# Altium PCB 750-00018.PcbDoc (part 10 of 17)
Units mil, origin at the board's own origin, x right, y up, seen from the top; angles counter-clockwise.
Board outline 7086.64 x 6299.21 mil, 8 copper layers (Top Layer, L2, L3, L4, L5, L6, L7, Bottom Layer), stack 60.6 mil thick; 1356 components, 1054 nets, 4851 pads, 4296 vias.
Unrouted connection lines stored in the file: 12.
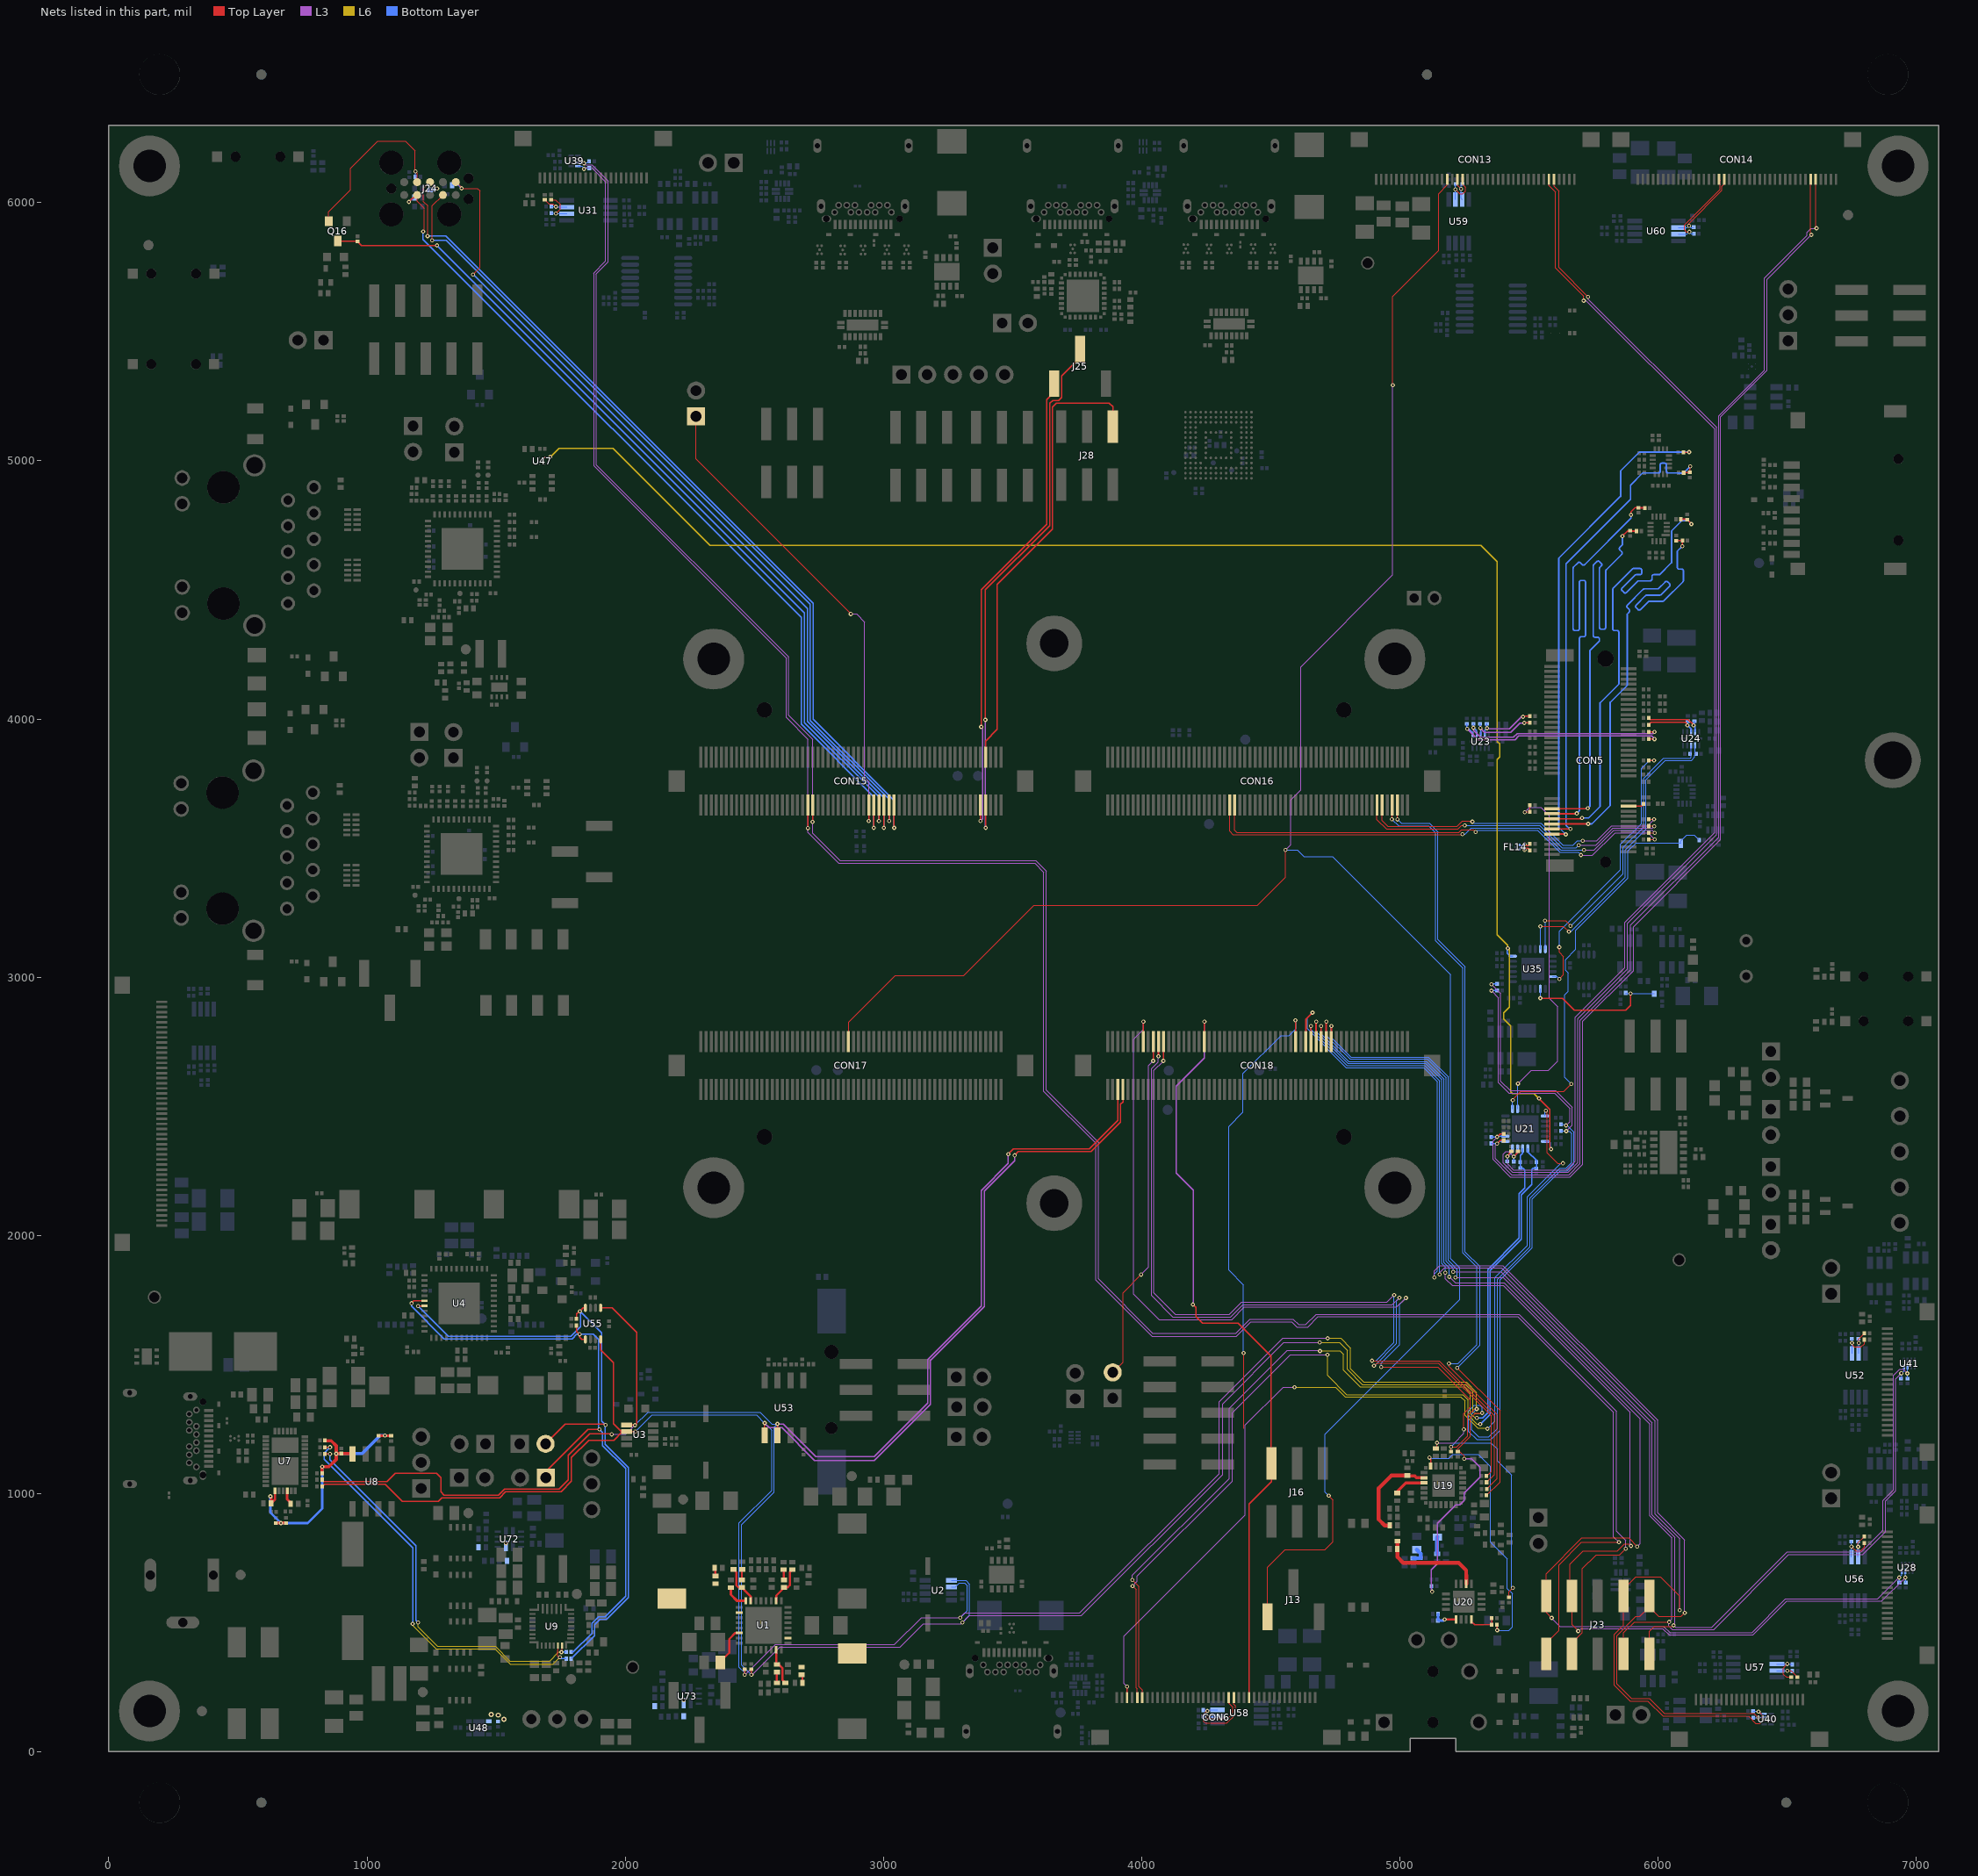
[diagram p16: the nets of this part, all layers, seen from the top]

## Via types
v1: diameter 16, hole 8, Top Layer to Bottom Layer, tented both sides, 3994 vias
v2: diameter 20, hole 10, Top Layer to Bottom Layer, tented both sides, 266 vias
v3: diameter 14, hole 7.87, Top Layer to Bottom Layer, tented both sides, 24 vias
v4: diameter 22, hole 12, Top Layer to Bottom Layer, tented both sides, 8 vias
v5: diameter 24, hole 12, Top Layer to Bottom Layer, tented both sides, 4 vias

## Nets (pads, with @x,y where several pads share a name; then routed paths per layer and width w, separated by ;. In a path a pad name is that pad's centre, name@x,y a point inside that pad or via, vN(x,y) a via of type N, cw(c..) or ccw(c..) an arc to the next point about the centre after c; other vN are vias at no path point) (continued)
"GPIO_C_5 / DSI_A_BL_EN / LVDS_A_BL_EN": CON6.27 CON18.82 J16.2 | length 3011.5
  Top Layer w5: v1(4198.33,1732.09) 4209.74,1720.68 4209.74,1685.04 4235.53,1659.26 4373.5,1659.26 4500.17,1532.59 4500.17,1118.66 J16.2@4501.95,1116.88 4501.95,1046.26 4415.76,960.06 CON6.27@4415.76,209.68
  Top Layer w6: CON18.82@4242.13,2750.44 v1@4242.13,2827.49
  L3 w5: v1(4198.33,1732.09) 4199.83,1733.59 4199.83,2175.39 4133.5,2241.71 4133.5,2577.65 4242.99,2687.14 v1(4242.99,2828.35)
"GPIO_C_6 / CAM_A_PWR": CON15.44 J23.1 R376.1 U39.4 | length 9216.5
  Top Layer w4: J23.1@5566.32,379.41 5566.32,421.21 5615.41,470.3 5615.41,723.87 5702.44,810.9 5847.78,810.9 v1(5848.36,811.47)
  Top Layer w5: CON15.44@2706.7,3666.88 2706.7,3577.98 v1(2707.58,3577.1)
  L3 w4: v1(1840,6130.2) 1845.27,6135.47 1869.47,6135.47 1924.42,6080.52 1924.42,5773.79 1877.84,5727.22 1877.84,4981.61 2623.28,4236.17 2623.28,4006.11 2707.58,3921.81 v1(2707.58,3577.1) 2707.58,3560.75 2826.66,3441.66 3585.75,3441.66 3620.92,3406.49 3620.92,2558.11 3822.26,2356.78 3822.26,1827.27 4039.82,1609.7 4366.02,1609.7 4421.93,1665.61 4580.38,1665.61 4600.61,1645.38 4643.06,1645.38 4683.35,1685.66 5456.19,1685.66 5827.71,1314.14 5827.71,832.12 v1(5848.36,811.47)
  Bottom Layer w4: U39.4@1816.76,6141.1 1831.06,6141.1 1840,6132.15 v1(1840,6130.2) 1843.92,6134.12 1860.57,6134.12 R376.1@1860.82,6133.87
"GPIO_C_7 / CAM_A_RST#": CON15.46 J23.3 R375.1 U39.3 | length 9149.4
  Top Layer w4: J23.3@5666.32,379.41 5666.32,420.46 5706.92,461.06 5706.92,709.15 5760.02,762.24 5851.24,762.24 v1(5874.7,785.7)
  Top Layer w5: v1(2725.36,3601.78) 2726.38,3602.8 CON15.46@2726.38,3666.88
  L3 w4: v1(1839.84,6152.52) 1845.9,6146.47 1871.08,6146.47 1933.34,6084.22 1933.34,5770.1 1886.76,5723.52 1886.76,4985.3 2632.2,4239.87 2632.2,4013.77 2725.36,3920.61 v1(2725.36,3601.78) 2725.36,3556.82 2830.81,3451.37 3590.29,3451.37 3631.29,3410.37 3631.29,2562.4 3832.62,2361.07 3832.62,1831.56 4042.72,1621.46 4364.67,1621.46 4419.08,1675.87 4586.65,1675.87 4608.24,1654.28 4635.43,1654.28 4675.46,1694.3 5462.2,1694.3 5838.11,1318.4 5838.11,854.32 5874.7,817.73 v1(5874.7,785.7)
  Bottom Layer w4: U39.3@1816.76,6154.88 1840.41,6154.88 v1@1840.41,6153.09 ; v1(1839.84,6152.52) v1@1840.41,6153.09 ; R375.1@1860.53,6159.56 1855.62,6154.65 1841.97,6154.65 v1@1840.41,6153.09
"GPIO_D_0 / CAM_B_PWR": CON18.32 J23.7 R390.1 U41.4 | length 5193.3
  Top Layer w4: J23.7@5866.32,379.41 5866.32,461.03 5908.15,502.86 v1(6042.9,502.86)
  Top Layer w6: CON18.32@4734.25,2750.44 v1@4734.25,2810.35
  L3 w4: v1(5214.71,1836.45) 5400.4,1836.45 5968.36,1268.48 5968.36,914.4 6053.57,829.19 6053.57,513.53 v1(6042.9,502.86) 6041.21,501.17 6041.21,486.9 6053.99,474.12 6215.71,474.12 6505.14,763.55 6792.34,763.55 6881.28,852.49 6881.28,971.54 6920.84,1011.1 6920.84,1444.95 v1(6941.53,1465.64)
  Bottom Layer w4: v1(4734.44,2810.54) 4734.44,2765.89 4809.53,2690.8 5110.02,2690.8 5187.68,2613.14 5187.68,1902.75 5222.33,1868.1 5222.33,1844.07 v1(5214.71,1836.45) ; R390.1@6940.39,1445.39 6941.53,1446.53 v1(6941.53,1465.64) 6943.69,1465.64 6952.6,1474.55 U41.4@6952.6,1490.47
"GPIO_D_1 / CAM_B_RST#": CON18.34 J23.9 R389.1 U41.3 | length 5155.3
  Top Layer w4: J23.9@5966.32,379.41 5966.32,467.43 5984.3,485.4 6056.14,485.4 v1(6060.21,489.46)
  Top Layer w6: CON18.34@4714.57,2750.44 v1@4714.57,2827.49
  L3 w4: v1(5206.68,1858.48) 5392.37,1858.48 5976.87,1273.98 5976.87,917.93 6064.32,830.47 6064.32,493.58 v1(6060.21,489.46) 6067.53,482.14 6208.53,482.14 6500.69,774.3 6787.89,774.3 6870.53,856.94 6870.53,974.01 6911.06,1014.54 6911.06,1457.52 6935.51,1481.97 6948.57,1481.97 6965.13,1465.4 v1(6965.13,1465.23)
  Bottom Layer w4: v1(4715.43,2828.35) 4715.43,2773.46 4806.18,2682.71 5106.67,2682.71 5179.6,2609.79 5179.6,1898.92 5206.68,1871.83 v1(5206.68,1858.48) ; R389.1@6965.54,1445.25 6965.13,1445.65 v1(6965.13,1465.23) 6966.38,1466.48 U41.3@6966.38,1490.47
"GPIO_D_2 / CAM_C_PWR": CON18.36 J23.2 R372.1 U28.4 | length 4991.3
  Top Layer w4: v1(5587.76,518.34) 5566.32,539.77 J23.2@5566.32,603.82 5566.32,689.88 5704.4,827.96 5886.37,827.96 5919.04,795.29 v1(5919.04,794.42)
  Top Layer w6: CON18.36@4694.88,2750.44 v1@4694.88,2810.35
  L3 w4: v1(5191.37,1839.43) 5214.35,1816.46 5403.16,1816.46 5930.69,1288.93 5930.69,806.07 v1(5919.04,794.42) ; v1(5587.76,518.34) 5619.98,486.12 6020.51,486.12 6045.62,461 6363.33,461 6494.11,591.79 6850.02,591.79 v1(6933.2,674.97)
  Bottom Layer w4: v1(4695.07,2810.54) 4695.07,2781.11 4802.45,2673.72 5102.95,2673.72 5170.61,2606.07 5170.61,1894.67 5191.37,1873.91 v1(5191.37,1839.43) ; R372.1@6934.29,655.18 6933.2,656.27 v1(6933.2,674.97) 6944.03,685.79 U28.4@6944.03,699.7
"GPIO_D_3 / CAM_C_RST#": CON18.38 J23.4 R371.1 U28.3 | length 4868.3
  Top Layer w4: v1(5690.38,467.57) 5666.32,491.63 J23.4@5666.32,603.82 5658.16,611.98 5658.16,725.87 5709.53,777.24 5841.97,777.24 5869.58,804.84 5887.01,804.84 v1(5894.59,797.26)
  Top Layer w6: CON18.38@4675.2,2750.44 v1@4675.2,2827.49
  L3 w4: v1(5176.06,1855.68) 5176.06,1832.36 5202.66,1805.76 5400.95,1805.76 5891.77,1314.95 5891.77,800.09 v1(5894.59,797.26) ; v1(5690.38,467.57) 5700.29,477.48 6016.93,477.48 6042.04,452.37 6366.9,452.37 6497.69,583.15 6865.93,583.15 v1(6957.55,674.77)
  Bottom Layer w4: v1(4676.06,2828.35) 4676.06,2788.77 4799.13,2665.7 5099.63,2665.7 5162.59,2602.74 5162.59,1890.81 5176.06,1877.33 v1(5176.06,1855.68) ; U28.3@6957.81,699.7 6957.81,675.03 v1(6957.55,674.77) 6959.63,672.69 R371.1@6959.63,655.18
"GPIO_D_4 / CAM_D_PWR": CON18.40 J23.8 R388.1 U40.4 | length 4706.2
  Top Layer w4: v1(6083.84,548.55) 6083.84,602.03 6008.83,677.04 5914.21,677.04 5866.32,629.15 J23.8@5866.32,603.82 5866.32,491.02 5830.57,455.27 5830.57,258.18 5891.97,196.78 5959.51,196.78 6018.39,137.9 6350.45,137.9 6377.99,110.37 6394.32,110.37 6403.97,120.02 6403.97,141.72 6390.55,155.14 v1(6388.84,155.14)
  Top Layer w6: CON18.40@4655.51,2750.44 v1@4655.51,2810.35
  L3 w4: v1(5154.03,1848.77) 5154.03,1855.74 5172.66,1874.37 5394.24,1874.37 5987.98,1280.63 5987.98,920.49 6083.84,824.63 v1(6083.84,548.55)
  Bottom Layer w4: v1(4655.7,2810.54) 4655.7,2797.03 4795.58,2657.14 5096.08,2657.14 5154.03,2599.2 v1(5154.03,1848.77) ; R388.1@6367.62,156.78 6387.19,156.78 v1(6388.84,155.14) 6396.73,147.25 U40.4@6410.66,147.25
"GPIO_D_5 / CAM_D_RST#": CON18.42 J23.10 R387.1 U40.3 | length 4731.7
  Top Layer w4: v1(6102.93,538.07) 6088.43,523.57 6002.5,523.57 5966.32,559.74 J23.10@5966.32,603.82 5966.32,560.37 5929.63,523.68 5913.86,523.68 5840.28,450.1 5840.28,262.96 5896.39,206.85 5966.23,206.85 6023.62,149.46 6370.92,149.46 v1(6388.01,132.37)
  Top Layer w6: CON18.42@4635.83,2750.44 4635.83,2837.04 v1(4661.33,2862.55)
  L3 w4: v1(5133.42,1837.07) 5133.42,1861.78 5154.44,1882.79 5399.28,1882.79 5998.47,1283.6 5998.47,924.83 6102.93,820.37 v1(6102.93,538.07)
  Bottom Layer w4: v1(4661.33,2862.55) 4641.35,2842.56 4641.35,2799.99 4792.25,2649.09 5092.75,2649.09 5145.97,2595.86 5145.97,1862.73 5133.42,1850.18 v1(5133.42,1837.07) ; R387.1@6367.8,131.26 6386.9,131.26 v1(6388.01,132.37) 6389.12,133.47 U40.3@6410.66,133.47
GPIO_D_6: CON15.113 J28.6 | length 1786
  Top Layer w5: CON15.113@3395.67,3851.92 3395.67,3914.9 3440.35,3959.57 3440.35,4520.83 3654.82,4735.31 3654.82,5208.47 3669.95,5223.6 3873.3,5223.6 3888.03,5208.87 J28.6@3888.03,5132.38
"GPIO_D_7 / SPI_C_CS1#": CON18.46 SB1.2 | length 1814.1
  Top Layer w4: v1(4394.43,1544.31) 4394.8,1543.94 4394.8,1252.38
  Top Layer w6: v1(4595,2832.55) 4596.46,2831.09 CON18.46@4596.46,2750.44
  Bottom Layer w4: v1(4394.43,1544.31) 4394.43,1807.47 4336.89,1865.01 4336.89,2421.82 4392.36,2477.29 4392.36,2627.49 4539.18,2774.32 4570.87,2774.32 4597.18,2800.63 4597.18,2830.37 v1(4595,2832.55)
HP_JD: R201.1 U19.12 | length 1039
  Top Layer w5: v1(5115.07,1139.27) 5119.48,1134.86 U19.12@5119.48,1106.54 ; R201.1@5375.56,492.02 5376.99,490.6 v1(5376.99,470.79)
  Bottom Layer w4: v1(5115.07,1139.27) 5118.54,1135.8 5188.57,1135.8 5204.01,1151.24 5303.63,1151.24 5350.45,1104.42 5350.45,812.1 5415.75,746.81 5415.75,632.18 5435.44,612.48 5435.44,483.25 5422.98,470.79 v1(5376.99,470.79)
HP_MICL1-: C212.1 U19.15 | length 123.7
  Top Layer w12: C212.1@4990.14,1002.22 4990.14,1008.5 5023.23,1041.58 U19.15@5093.89,1041.58
HPL: C202.2 FB5.1 R187.1 | length 65.7
  Bottom Layer w15: FB5.1@5144.76,766.45 5143.98,767.23 R187.1@5143.98,797.72 5143.98,830.76 C202.2@5144.76,831.54
HPR: C203.2 FB6.1 R191.2 | length 68.3
  Bottom Layer w15: FB6.1@5051.89,749.67 5079.87,749.67 R191.2@5081.16,750.96 5081.16,767.01 C203.2@5065.31,782.86
I2C_A_SCL: CON18.115 R17.1 R55.2 R190.1 R192.1 R302.1 R329.1 U2.5 U3.5 U53.6 U55.5 | length 13471.4
  Top Layer w4: v1(5248.47,1134.73) 5248.47,1146.01 5232.4,1162.08 R190.1@5224,1162.08 5224,1172.23 5273.41,1221.64 5273.41,1293.16 5292.6,1312.35 v1(5318.83,1312.35)
  Top Layer w5: R55.2@826.11,1053.79 832.76,1047.14 1077.32,1047.14 1108.54,1078.36 1269.94,1078.36 1286.03,1062.27 1286.03,1007.14 1298.84,994.32 1509.45,994.32 1532.37,1017.24 1742.98,1017.24 1778.7,1052.95 1778.7,1148.02 1861.84,1231.17 1945.1,1231.17 v1(1946.94,1229.33) ; U55.5@1904.57,1719.36 1948.59,1719.36 2044.02,1623.93 2044.02,1270.91 2038.85,1265.74 U3.5@2005.39,1265.74 ; R17.1@2488.19,319.89 2488.19,298.95 v1(2488.58,298.56) ; v1(2589.11,1269.85) 2589.85,1269.1 U53.6@2589.85,1225.9 ; v1(3483.35,2314.83) 3503.1,2334.59 3797.35,2334.59 3907.48,2444.72 CON18.115@3907.48,2565.4
  L3 w4: v1(1946.94,1229.33) 2002.44,1229.33 v1(2037.97,1264.86) ; v1(2488.58,298.56) 2491.12,298.56 2598.09,405.54 3063.65,405.54 3154.42,496.31 3300.85,496.31 v1(3305.5,500.95) 3332.57,528.02 3766.81,528.02 4313.06,1074.27 4313.06,1346.82 4550.98,1584.75 v1(4689.97,1584.75) ; v1(5353.98,2947.81) 5381.4,2920.39 5381.4,2592.24 5422.58,2551.06 5598.81,2551.06 5657.93,2491.94 5657.93,2440.42 v1(5643.4,2425.89)
  L3 w5: v1(2589.11,1269.85) 2612.13,1269.85 2738.2,1143.78 2964,1143.78 3171.24,1351.02 3171.24,1518.95 3378.88,1726.59 3378.88,2173.61 3483.35,2278.08 v1(3483.35,2314.83) ; v1(5125.07,620.18) 5122.03,623.22 5122.03,705.14 5144.76,727.86 5144.76,884.6 5216.26,956.1 5231.17,956.1 5248.08,973.01 5248.08,1002.63 5309.26,1063.8 5309.26,1103.14 5277.67,1134.73 v1(5248.47,1134.73)
  L6 w4: v1(4689.97,1584.75) 4766.15,1584.75 4796.07,1554.83 4796.07,1481.29 4854.53,1422.83 5254.07,1422.83 5282.65,1394.25 5282.65,1317.18 5290.66,1309.18 5315.65,1309.18 v1(5318.83,1312.35)
  Bottom Layer w4: v1(2037.97,1264.86) 2088.82,1315.71 2521.83,1315.71 2567.7,1269.85 v1(2589.11,1269.85) 2577.19,1257.93 2577.19,1006.18 2451.42,880.4 2451.42,335.72 v1(2488.58,298.56) ; U2.5@3263.47,663.75 3318.77,663.75 3333.19,649.34 3333.19,528.64 v1(3305.5,500.95) ; v1(5318.83,1312.35) 5318.83,1333.75 5310.01,1342.57 5288.1,1342.57 5266.19,1320.66 5266.19,1240.95 5297.99,1209.14 5352.22,1209.14 5389,1245.92 5389,1829 5512.71,1952.72 5512.71,2141.39 5621.8,2250.48 5647.58,2250.48 5674.26,2277.16 5674.26,2399.03 5643.3,2429.99 R302.1@5623.53,2429.99
  Bottom Layer w5: R192.1@5122.6,641.5 5122.6,622.66 v1(5125.07,620.18) ; v1@5354.77,2948.6 R329.1@5376.29,2948.6
I2C_A_SCL_3V3: J37.2 R280.2 R436.1 U4.43 U55.8 | length 2633.3
  Top Layer w5: v1(1197.45,1726.46) 1198.03,1727.04 U4.43@1222.82,1727.04 ; J37.2@1691.42,1192.67 1766.96,1268.2 1920.47,1268.2 v1(1923.18,1265.49) ; R436.1@1812.27,1676.84 1812.27,1695.02 1823.64,1706.39 v1(1824.31,1706.39) 1824.31,1707.06 1836.61,1719.36 U55.8@1845.52,1719.36
  Bottom Layer w5: v1(1197.45,1726.46) 1197.89,1726.02 1314.63,1609.28 1789.13,1609.28 1826.78,1646.92 v1@1826.78,1703.92 ; R280.2@1790.69,360.59 1791.15,360.59 1880.92,450.36 1880.92,492.81 1901.05,512.94 1926.72,512.94 2011.96,598.18 2011.96,1101.04 1922.39,1190.61 1922.39,1264.7 v1(1923.18,1265.49) 1907.53,1281.14 1907.53,1623.17 v1@1826.78,1703.92 ; v1(1824.31,1706.39) v1@1826.78,1703.92
I2C_A_SDA: CON18.113 R16.1 R56.2 R189.1 R194.1 R209.1 R328.1 U2.6 U3.6 U53.5 U55.4 | length 13267.2
  Top Layer w4: R189.1@5198.09,1162.38 5198.09,1180.27 v1(5197.75,1180.61) 5220.12,1180.61 5263.05,1223.55 5263.05,1302.62 5287.99,1327.56 v1(5297.26,1327.56) ; R194.1@5422.49,598.18 5422.49,619.85 v1(5437.17,634.53)
  Top Layer w5: R56.2@826.11,1027.67 835.3,1036.87 1070.16,1036.87 1136.8,970.22 1275.09,970.22 1288.92,984.05 1513.2,984.05 1536.48,1007.33 1751.12,1007.33 1790.94,1047.15 1790.94,1138.99 1858.63,1206.68 1955.57,1206.68 1989.05,1240.15 1985.06,1240.15 1953.68,1271.53 1953.68,1507.86 1904.57,1556.96 U55.4@1904.57,1597.31 ; U3.6@2005.39,1240.15 2038.51,1240.15 v1(2038.65,1240.01) ; R16.1@2462.44,320.07 2462.44,298.5 v1(2462.51,298.43) ; v1(2539.67,1273.24) 2539.85,1273.05 U53.5@2539.85,1225.9 ; v1(3507.75,2309.95) 3522.12,2324.32 3804.28,2324.32 3918.21,2438.25 3918.21,2508.66 3927.17,2517.62 CON18.113@3927.17,2565.4
  L3 w4: v1(2462.51,298.43) 2464.99,298.43 2581.54,414.98 3042.76,414.98 3147.45,519.66 v1(3297.18,519.66) 3314.69,537.17 3759.69,537.17 4300.24,1077.72 4300.24,1355.52 4546.17,1601.45 v1(4720.42,1601.45) ; v1(5354.14,2972.85) 5390.36,2936.63 5390.36,2596.94 5426.87,2560.43 5603.1,2560.43 5667.11,2496.42 5667.11,2426.63 v1(5644.02,2403.53)
  L3 w5: v1(2539.67,1273.24) 2558.3,1254.61 2606.75,1254.61 2732.76,1128.6 2963.48,1128.6 3181.07,1346.19 3181.07,1515.28 3391.16,1725.36 3391.16,2171.81 3507.75,2288.41 v1(3507.75,2309.95)
  L6 w4: v1(4720.42,1601.45) 4771.03,1601.45 4808.81,1563.67 4808.81,1482.99 4860.21,1431.6 5257.9,1431.6 5297.26,1392.24 v1(5297.26,1327.56)
  Bottom Layer w4: v1(2038.65,1240.01) 2103.34,1304.71 2508.2,1304.71 v1(2539.67,1273.24) 2567.6,1245.31 2567.6,1012.45 2441.28,886.14 2441.28,327.97 2462.51,306.75 v1(2462.51,298.43) ; U2.6@3263.47,638.16 3277.86,638.16 3293.18,653.49 3313.61,653.49 3323.84,643.26 3323.84,546.32 v1(3297.18,519.66) ; v1(5197.75,1180.61) 5213.84,1196.7 5352.75,1196.7 5377.53,1171.92 5377.53,1126.6 5433.08,1071.05 5433.08,638.63 v1(5437.17,634.53) ; v1(5297.26,1327.56) 5277.99,1308.29 5277.99,1246.42 5305.48,1218.93 5344.84,1218.93 5378.01,1252.1 5378.01,1830.75 5503.65,1956.39 5503.65,2144.44 5619.75,2260.54 5643.81,2260.54 5665.72,2282.45 5665.72,2394.37 5656.56,2403.53 v1(5644.02,2403.53) 5643,2404.55 R209.1@5623.53,2404.55
  Bottom Layer w5: v1@5354.92,2973.64 R328.1@5376.29,2973.64
I2C_A_SDA_3V3: J42.1 R278.2 R435.1 U4.42 U55.1 | length 2594.5
  Top Layer w5: v1(1171.82,1737.08) 1181.47,1746.73 U4.42@1222.82,1746.73 ; J42.1@1692.8,1061.54 1692.8,1086.23 1855.28,1248.72 v1(1900.08,1248.72) ; R435.1@1812.27,1650.9 1812.27,1628.11 v1(1823.41,1616.97) 1823.41,1605.72 1831.82,1597.31 U55.1@1845.52,1597.31
  Bottom Layer w5: v1(1171.82,1737.08) 1171.82,1725.63 1298.83,1598.63 1793.79,1598.63 1812.14,1616.97 v1(1823.41,1616.97) 1876.36,1616.97 1896.93,1596.4 1896.93,1251.86 v1(1900.08,1248.72) 1911.97,1236.82 1911.97,1186.05 2001.36,1096.65 2001.36,602.57 1922.33,523.54 1896.66,523.54 1870.32,497.2 1870.32,458.67 1798.54,386.89 R278.2@1790.78,386.89
I2C_B_MCU_SCL: CON15.112 J25.1 | length 1918.4
  Top Layer w5: v1@3375.99,3604.75 CON15.112@3375.99,3666.88 ; v1(3378.34,3969.56) 3378.34,4499.97 3632.68,4754.32 3632.68,5236.59 3660.62,5264.52 J25.1@3660.62,5338.03
  L3 w5: v1(3375.89,3604.65) 3384.33,3613.09 3384.33,3963.56 v1(3378.34,3969.56)
I2C_B_MCU_SDA: CON15.114 J25.2 | length 2149.6
  Top Layer w5: v1(3394.75,3996.64) 3394.75,4500.57 3643.87,4749.69 3643.87,5222.67 3655.25,5234.05 3678.04,5234.05 3689.91,5245.92 3689.91,5329.08 3761.23,5400.39 J25.2@3761.23,5432.54 ; v1(3395.58,3578.53) 3395.67,3578.62 CON15.114@3395.67,3666.88 ; J25.2@3760.56,5432.54 J25.2@3760.56,5471.94
  L3 w5: v1(3394.75,3996.64) 3394.75,3584.95 3391.96,3582.15 v1(3395.58,3578.53)
I2C_C_SCL: CON6.23 R492.2 U58.2 | length 232.9
  Top Layer w4: v1(4254.45,134.72) 4254.45,130.78 4256.58,128.65 4333.13,128.65 4353,148.53 4353,172.17 4337.02,188.16 CON6.23@4337.02,209.68
  Bottom Layer w4: R492.2@4242.18,135.83 4243.25,136.9 4252.27,136.9 v1(4254.45,134.72) 4256.62,136.9 U58.2@4293.42,136.9
I2C_C_SDA: CON6.24 R491.2 U58.3 | length 311.5
  Top Layer w4: v1(4254.09,158.01) 4251.61,158.01 4239.65,146.05 4239.65,117.8 4246.77,110.68 4330.02,110.68 4362.73,143.39 4362.73,178.33 4356.7,184.36 CON6.24@4356.7,209.68
  Bottom Layer w4: R491.2@4242.18,161.22 4243.46,162.5 4249.6,162.5 v1(4254.09,158.01) 4258.58,162.5 U58.3@4293.42,162.5
I2C_CAM_A_SCL: R367.1 R453.2 U31.2 | length 145.5
  Top Layer w4: R367.1@1712.84,6011.06 1730.03,6011.06 1748.21,5992.88 1748.21,5974.4 v1(1731.81,5958)
  Bottom Layer w4: R453.2@1713.15,5958.85 1730.96,5958.85 v1(1731.81,5958) 1732.31,5957.5 1772.87,5957.5 U31.2@1773.32,5957.05
I2C_CAM_A_SDA: R368.1 R452.2 U31.3 | length 115
  Top Layer w4: R368.1@1688.35,6010.86 1703.67,5995.55 1719.88,5995.55 v1(1731.55,5983.88)
  Bottom Layer w4: R452.2@1713.36,5984.34 1731.09,5984.34 v1(1731.55,5983.88) 1732.78,5982.65 U31.3@1773.32,5982.65
I2C_CAM_B_SCL: R379.1 R455.2 U52.2 | length 134.5
  Top Layer w4: v1(6750.93,1583.05) 6750.93,1576.08 6758.95,1568.06 6786.55,1568.06 6799,1580.51 R379.1@6799,1596
  Bottom Layer w4: R455.2@6750.15,1597.79 6751.09,1596.85 U52.2@6751.09,1542.72
I2C_CAM_B_SDA: R380.1 R454.2 U52.3 | length 102.1
  Top Layer w4: v1(6776.84,1583.05) 6776.84,1598.59 R380.1@6798.83,1620.58
  Bottom Layer w4: R454.2@6775.81,1597.79 6776.69,1596.91 U52.3@6776.69,1542.72
I2C_CAM_C_SCL: R369.1 R457.2 U56.2 | length 140.5
  Top Layer w4: v1(6748.89,794.67) 6766.54,777.02 6783.41,777.02 6798.54,792.15 R369.1@6798.54,808.66
  Bottom Layer w4: R457.2@6748.76,814.83 6748.76,794.8 v1(6748.89,794.67) 6749.06,794.5 U56.2@6749.06,754.21
I2C_CAM_C_SDA: R370.1 R456.2 U56.3 | length 110.1
  Top Layer w4: v1(6774.63,794.03) 6774.63,809.69 R370.1@6798.54,833.59
  Bottom Layer w4: R456.2@6774.29,814.66 6774.29,794.37 v1(6774.63,794.03) U56.3@6774.66,754.21
I2C_CAM_D_SCL: R381.1 R459.2 U57.2 | length 142.7
  Top Layer w4: v1(6500.49,340.24) 6484.55,324.3 6484.55,300.81 6496.3,289.06 R381.1@6515.2,289.06
  Bottom Layer w4: U57.2@6459.98,339.78 6500.03,339.78 v1(6500.49,340.24) 6502.44,338.28 R459.2@6520.18,338.28
I2C_CAM_D_SDA: R382.1 R458.2 U57.3 | length 109.3
  Top Layer w4: v1(6500.33,313.42) 6514.69,313.42 R382.1@6539.01,289.09
  Bottom Layer w4: U57.3@6459.98,314.18 6499.57,314.18 v1(6500.33,313.42) R458.2@6520.17,313.42
I2C_charger_SCL: R210.2 R280.1 U9.14 | length 1587.4
  Top Layer w4: U9.14@1739.2,411.75 1739.2,395.9 1737.6,394.3 1737.6,368.93 1740.68,365.84 v1(1746.36,365.84)
  Top Layer w5: R210.2@837.1,1179.45 v1(856.52,1179.45)
  L6 w4: v1(1176.44,495.35) 1176.44,490.99 1268.13,399.3 1494.41,399.3 1554.62,339.09 1719.61,339.09 v1(1746.36,365.84)
  Bottom Layer w5: v1(856.52,1179.45) 834.28,1157.21 834.28,1133.58 1177.92,789.94 1177.92,496.82 v1(1176.44,495.35) ; v1@1745.93,365.41 1745.93,360.59 R280.1@1771.01,360.59
I2C_charger_SDA: R273.2 R278.1 U9.15 | length 1501.2
  Top Layer w4: v1(1752.61,386.06) 1754.05,386.06 1754.94,386.96 U9.15@1754.94,411.75
  Top Layer w5: R273.2@837.1,1153.58 v1(856.52,1153.58)
  L6 w4: v1(1197.7,500.55) 1197.7,482.96 1272.55,408.12 1496.99,408.12 1553.35,351.75 1708.2,351.75 1742.51,386.06 v1(1752.61,386.06)
  Bottom Layer w5: v1(856.52,1153.58) 856.52,1131.27 1188.89,798.9 1188.89,509.36 v1(1197.7,500.55) ; v1(1752.61,386.06) 1753.43,386.89 R278.1@1771.1,386.89
I2C_D_SCL: CON13.23 R496.2 U59.2 | length 199.4
  Top Layer w4: v1(5215.17,6051.17) 5232.69,6033.64 5243.52,6033.64 5254.35,6044.47 5254.35,6059.43 5242.4,6071.38 CON13.23@5242.4,6089.26
  Bottom Layer w4: v1(5215.17,6051.17) 5215.31,6051.03 U59.2@5215.31,6012.35 5215.31,6070.7 R496.2@5216.35,6071.75
I2C_D_SDA: CON13.24 R495.2 U59.3 | length 105.7
  Top Layer w4: CON13.24@5222.72,6089.26 5222.72,6066.69 v1(5236.51,6052.89)
  Bottom Layer w4: U59.3@5240.91,6012.35 5236.51,6016.74 v1(5236.51,6052.89) 5236.51,6065.93 R495.2@5242.33,6071.75
I2C_E_SCL: CON14.23 R501.2 U60.2 | length 305
  Top Layer w4: v1(6119.24,5910.03) 6117.8,5911.48 6117.8,5917.56 6247.63,6047.39 6247.63,6063.76 6255.81,6071.95 CON14.23@6255.81,6090.59
  Bottom Layer w4: U60.2@6078.35,5902.95 6112.15,5902.95 v1(6119.24,5910.03) 6126.65,5902.63 6135.62,5902.63 R501.2@6137.99,5905
I2C_E_SDA: CON14.24 R500.2 U60.3 | length 343.3
  Top Layer w4: v1(6120.68,5886.85) 6109.1,5886.85 6101.88,5894.07 6101.88,5914.24 6239.17,6051.53 6239.17,6087.55 CON14.24@6236.13,6090.59
  Bottom Layer w4: U60.3@6078.35,5877.35 6111.18,5877.35 v1(6120.68,5886.85) 6128.22,5879.31 R500.2@6138.14,5879.31
I2S_A_BITCLK: CON16.116 R184.1 | length 2996.3
  Top Layer w4: CON16.116@4990.16,3666.88 4990.16,3611.6 v1(4990.63,3611.13) ; v1(5221.44,1486.98) 5387.46,1320.95 5387.46,1045.08 R184.1@5335.45,993.06
  Bottom Layer w4: v1(4990.63,3611.13) 5005.74,3596.01 5114.27,3596.01 5147.58,3562.7 5147.58,3145.01 5252.51,3040.08 5252.51,1935.67 5309.27,1878.92 5309.27,1574.81 v1(5221.44,1486.98)
I2S_A_DATA_IN: CON18.98 R186.1 | length 3118.1
  Top Layer w4: v1(4891.59,1514.64) 5152.32,1514.64 5366.35,1300.62 5366.35,1074.21 R186.1@5335.97,1043.83
  Top Layer w6: v1@4084.65,2676.53 CON18.98@4084.65,2750.44 CON18.98@4084.65,2753.58
  L3 w4: v1(4083.78,2675.67) 4047.51,2639.4 4047.51,1776.57 4130.39,1693.69 4339.87,1693.69 4387.15,1740.97 4949.68,1740.97 v1(4977.58,1768.87)
  Bottom Layer w4: v1(4891.59,1514.64) 4906.5,1514.64 4977.58,1585.72 v1(4977.58,1768.87)
I2S_A_DATA_OUT: CON18.100 R185.1 | length 3116.5
  Top Layer w4: v1(4899.63,1495.21) 4910.58,1506.16 5148.93,1506.16 5354.58,1300.51 5354.58,1085.1 5337.99,1068.5 R185.1@5335.04,1068.5
  Top Layer w6: v1@4064.96,2693.67 CON18.100@4064.96,2753.58
  L3 w4: v1(4064.77,2693.48) 4064.77,2672.37 4037.64,2645.24 4037.64,1766.35 4120.42,1683.56 4344.03,1683.56 4391.86,1731.39 4970.5,1731.39 v1(4998.15,1759.03)
  Bottom Layer w4: v1(4899.63,1495.21) 4901.42,1495.21 4987.53,1581.32 4987.53,1748.41 v1(4998.15,1759.03)
I2S_A_LRCLK: CON16.114 R183.1 | length 3013.3
  Top Layer w4: v1(4968.96,3611.81) 4969.81,3612.66 4969.81,3666.22 CON16.114@4970.47,3666.88 ; v1(5189.97,1503.82) 5189.97,1493.44 5376.68,1306.73 5376.68,1058.77 R183.1@5335.86,1017.94
  Bottom Layer w4: v1(4968.96,3611.81) 4995.42,3585.35 5111.33,3585.35 5137.96,3558.71 5137.96,3141.03 5243.67,3035.32 5243.67,1932.05 5298.16,1877.55 5298.16,1577.18 5224.81,1503.82 v1(5189.97,1503.82)
I2S_AB_MCLK: CON18.106 R419.2 | length 3268.1
  Top Layer w4: v1(4927.33,1489.63) 5147.13,1489.63 5273.52,1363.24 5273.52,1335.76 5247.78,1310.03 v1(5247.78,1248.39) ; R419.2@5139.83,1174.31 5143.2,1177.68 v1(5143.2,1196.53)
  Top Layer w6: CON18.106@4005.91,2750.44 v1@4005.91,2827.49
  L3 w4: v1(4006.77,2828.35) 4006.77,2798.03 3968.96,2760.22 3968.96,1772.93 4067.53,1674.35 4349.11,1674.35 4396.87,1722.11 4987.84,1722.11 v1(5023.35,1757.62) ; v1(5143.2,1196.53) 5210.93,1196.53 5247.78,1233.37 v1(5247.78,1248.39)
  Bottom Layer w4: v1(4927.33,1489.63) 4927.33,1505.8 4998.66,1577.13 4998.66,1732.93 v1(5023.35,1757.62)
"I2S_AB_RST / GPIO_A_5": CON18.102 J39.2 | length 1348.2
  Top Layer w4: J39.2@3887.85,1469.4 3927.17,1508.71 3927.17,1777.58 v1(3997.76,1848.17)
  Top Layer w6: v1@4045.28,2676.53 CON18.102@4045.28,2750.44 CON18.102@4045.28,2753.58
  L3 w4: v1(3997.76,1848.17) 4027.38,1877.79 4027.38,2658.64 v1(4044.41,2675.67)
I2S_B_BITCLK: CON16.52 R268.1 | length 1848.6
  Top Layer w4: CON16.52@4360.24,3666.88 4360.24,3568.87 4368.19,3560.91 5228.11,3560.91 5237.87,3570.68 5284.98,3570.68 v1(5293.3,3562.36) ; R268.1@5963.24,3533.91 5986.31,3533.91 v1(5986.45,3533.77)
  L3 w4: v1(5700.98,3472.96) 5702.49,3471.45 5745.08,3471.45 5833.16,3559.53 5960.69,3559.53 v1(5986.45,3533.77)
  Bottom Layer w4: v1(5293.3,3562.36) 5299.89,3568.95 5533.57,3568.95 5619.16,3483.36 5690.59,3483.36 v1(5700.98,3472.96)
I2S_B_DATA_IN: CON16.108 R266.1 | length 1242.9
  Top Layer w4: CON16.108@4911.42,3666.88 4911.42,3610.31 4947.71,3574.02 5225.23,3574.02 5239.53,3588.32 v1(5251.13,3588.32) ; R266.1@5963.14,3585.33 5983.75,3585.33 v1(5984.62,3584.45)
  L3 w4: v1(5692.33,3511.34) 5758.86,3511.34 5824.76,3577.24 5977.4,3577.24 v1(5984.62,3584.45)
  Bottom Layer w4: v1(5251.13,3588.32) 5252.19,3587.26 5541.99,3587.26 5627.71,3501.54 5682.53,3501.54 v1(5692.33,3511.34)
I2S_B_DATA_OUT: CON16.110 R265.1 | length 1232.1
  Top Layer w4: CON16.110@4931.1,3666.88 4931.1,3606.29 4952.53,3584.87 5221.39,3584.87 5241.59,3605.07 5277.8,3605.07 v1(5280.66,3602.21) ; R265.1@5963.22,3611.33 5984.04,3611.33 v1(5984.19,3611.17)
  L3 w4: v1(5708.23,3528.69) 5763.07,3528.69 5820.38,3586 5959.02,3586 v1(5984.19,3611.17)
  Bottom Layer w4: v1(5280.66,3602.21) 5287.09,3595.78 5546.32,3595.78 5630.71,3511.39 5670.44,3511.39 5687.74,3528.69 v1(5708.23,3528.69)
I2S_B_LRCLK: CON16.50 R267.1 | length 1858.1
  Top Layer w4: CON16.50@4340.55,3666.88 4340.55,3565.07 4353.83,3551.79 5239.91,3551.79 v1(5241.62,3553.5) ; R267.1@5963.04,3559.47 v1@5985.85,3559.47
  L3 w4: v1(5713.3,3492.38) 5752.94,3492.38 5829.37,3568.81 5976.52,3568.81 v1(5986.3,3559.04)
  Bottom Layer w4: v1(5241.62,3553.5) 5252.19,3553.5 5276.92,3578.23 5537.42,3578.23 5623.26,3492.38 v1(5713.3,3492.38)
INT_B: R195.2 R198.2 U20.13 | length 97.4
  Top Layer w10: v1@5173.12,512.44 U20.13@5217.48,512.44
  Bottom Layer w10: R198.2@5147,533.59 R195.2@5147,508.39 5169.06,508.39 v1(5173.12,512.45)
IO_exp_reset: U21.12 U35.24 U47.4 | length 6417.5
  Top Layer w5: U47.4@1687.75,5014.54 1709.69,5014.54 v1(1709.9,5014.76) ; v1@5538.75,2530.19 5580.61,2488.32 5580.61,2339.45 v1(5585.89,2334.17)
  L6 w5: v1(1709.9,5014.76) 1743.63,5048.48 1952.38,5048.48 2328.45,4672.41 5313.63,4672.41 5376.97,4609.06 5376.97,3912.98 5386.67,3903.28 5386.67,3852.74 5376.97,3843.05 5376.97,3165.26 5417.82,3124.42 v1(5417.82,3111.97) 5423.69,3106.1 5423.69,2884.54 5401.87,2862.72 5401.87,2837.7 5429.38,2810.18 5429.38,2555.43 5435.67,2549.14 5519.97,2549.14 v1(5538.75,2530.36)
  Bottom Layer w5: v1(5417.82,3111.97) 5415.98,3110.14 5415.98,3092.84 5427.75,3081.08 U35.24@5437.38,3081.08 ; U21.12@5562.04,2363.96 5578.37,2363.96 5582.93,2359.4 5582.93,2337.13 v1(5585.89,2334.17)
JTAG_nTRST: CON15.72 Q16.3 R366.2 | length 3390.1
  Top Layer w5: Q16.3@886.36,5851.03 R366.2@961.19,5851.03 ; R366.2@962.64,5849.58 977.95,5834.27 v1(1271.02,5834.27) ; v1@2982.29,3604.75 CON15.72@2982.29,3666.88
  Bottom Layer w5: v1(1271.02,5834.27) 2694.23,4411.06 2694.23,3985.87 2982.19,3697.91 v1(2982.19,3604.65)
JTAG_RESET: J24.9 Q16.2 R322.2 | length 694.4
  Top Layer w4: Q16.2@851.36,5928.03 851.36,5964.39 936.08,6049.11 936.08,6132.43 1041.61,6237.97 1148.95,6237.97 1185.81,6201.1 1185.81,6122.24 v1(1187.1,6120.95) 1193.79,6114.27 J24.9@1193.79,6079.38
  Bottom Layer w4: v1(1187.1,6120.95) 1187.32,6120.73 R322.2@1187.32,6099.9
JTAG_RTCK: CON15.68 J47.1 | length 1919.6
  Top Layer w4: J47.1@2274.06,5171.96 2274.06,5007.22 2873.44,4407.84 v1(2873.44,4406.68)
  Top Layer w5: v1@2942.92,3604.75 CON15.68@2942.92,3666.88
  L3 w4: v1(2873.44,4406.68) 2895.88,4406.68 2926.85,4375.71 2926.85,3772.96 2942.82,3756.99 v1(2942.82,3604.65)
JTAG_TCK(SWCLK): CON15.76 J24.4 | length 3269.1
  Top Layer w4: v1(1251.89,5854.11) 1251.89,5987.48 J24.4@1293.79,6029.38
  Top Layer w5: v1@3021.66,3604.75 CON15.76@3021.66,3666.88
  Bottom Layer w5: v1(1251.89,5854.11) 1252.16,5853.84 1306.61,5853.84 2716.25,4444.2 2716.25,3994.99 3021.56,3689.67 v1(3021.56,3604.65)
JTAG_TDI: CON15.78 J24.8 R323.1 | length 3463.8
  Top Layer w4: v1(1234.5,5870.4) 1234.81,5870.71 1234.81,5987.78 1218.93,6003.66 1218.93,6054.52 J24.8@1243.79,6079.38 1268.33,6054.84 v1(1271.39,6054.84)
  Top Layer w5: v1(3041.25,3578.53) 3041.34,3578.62 CON15.78@3041.34,3666.88
  Bottom Layer w5: v1(1234.5,5870.4) 1305.23,5870.4 2726.98,4448.65 2726.98,3999.43 3041.25,3685.17 v1(3041.25,3578.53) ; R323.1@1243.79,6049.11 1265.66,6049.11 v1(1271.39,6054.84)
JTAG_TDO(SWO): CON15.74 J24.6 R324.1 | length 3375.6
  Top Layer w4: J24.6@1343.79,6079.38 1365.99,6057.18 v1(1365.99,6055.39) 1426.94,6055.39 1436.7,6045.63 1436.7,5747.97 v1(1410.47,5721.74)
  Top Layer w5: v1(3001.88,3578.53) 3001.97,3578.62 CON15.74@3001.97,3666.88
  Bottom Layer w5: R324.1@1329.35,6067.47 1353.91,6067.47 v1(1365.99,6055.39) ; v1(1410.47,5721.74) 1411.24,5721.74 2705.52,4427.47 2705.52,3990.54 3001.88,3694.18 v1(3001.88,3578.53)
JTAG_TMS(SWDIO): CON15.70 J24.2 R320.1 | length 3346.2
  Top Layer w4: J24.2@1193.79,6029.38 1193.79,6005.05 1221.01,5977.83 1221.01,5891.56 v1(1217.13,5887.68)
  Top Layer w5: v1(1162.2,6002.77) 1188.81,6029.38 J24.2@1193.79,6029.38 ; v1(2962.51,3578.53) CON15.70@2962.51,3666.78
  Bottom Layer w5: v1(1162.2,6002.77) 1171,6011.57 1176.31,6011.57 R320.1@1184.03,6019.29 ; v1(1217.13,5887.68) 1217.13,5858.22 2681.06,4394.29 2681.06,3980.41 2962.51,3698.97 v1(2962.51,3578.53)
LDO_1V5: C81.2 U7.4 | length 52.5
  Top Layer w10: U7.4@690.73,1010.71 690.73,977.64 C81.2@704.45,963.91
LDO_3V3: C80.2 C87.1 R57.2 R58.2 R59.2 R60.2 R63.1 R64.1 U7.1 U8.8 | length 1108.8
  Top Layer w10: v1(625.65,989.42) 628.43,986.64 C80.2@628.43,962.28 643.48,977.33 U7.1@643.48,1010.71 ; R64.1@1050,1224.19 1069.19,1224.19 v1(1069.57,1224.57) 1070.22,1223.92 R63.1@1093.31,1223.92
  Top Layer w12: R60.2@647.27,885.88 v1(666.58,885.88) R59.2@685.88,885.88 ; R57.2@826.11,1078.96 v1(826.11,1103.8) 852.53,1103.8 880.64,1131.91 v1(880.64,1154.49) ; R58.2@837.1,1205.65 838.13,1204.62 861.08,1204.62 880.64,1185.06 v1(880.64,1154.49) ; C87.1@900.05,1155.08 881.23,1155.08 v1(880.64,1154.49) ; C87.1@900.3,1155.33 942.32,1155.33 U8.8@944.22,1153.44
  Bottom Layer w10: v1(625.65,989.42) 625.65,926.81 v1(666.58,885.88) 770.39,885.88 826.11,941.6 v1(826.11,1103.8)
  Bottom Layer w12: v1@880.96,1154.49 980.73,1154.49 1050.81,1224.57 v1(1069.57,1224.57)
LS_12V: R193.1 R200.1 R260.1 R272.1 R556.2 U48.1 U72.2 U73.2
  other v1: 2226.34,199.69 1537.29,807.65
  other v2: 1530.62,125.73 1508.14,141.81 1480.65,143.9
LVDS_C_HPD: CON6.6 R540.1 R548.2 U21.16 | length 3683.3
  Top Layer w4: v1(3963.67,665.73) 3988.93,640.47 3988.93,251.77 4002.37,238.33 CON6.6@4002.37,209.68
  L3 w4: v1(3963.67,665.73) 3963.67,683.6 4338.81,1058.74 4338.81,1329.54 4564.28,1555.01 4687.31,1555.01 v1(4690.24,1552.08)
  L6 w4: v1(4690.24,1552.08) 4767.68,1552.08 4781.21,1538.55 4781.21,1478.04 4846.57,1412.69 5248.08,1412.69 5273.4,1387.36 5273.4,1310.47 5291.51,1292.36 v1(5298.54,1292.36)
  Bottom Layer w5: v1(5298.54,1292.36) 5319.46,1292.36 5340.18,1313.08 5340.18,1867.52 5461.63,1988.97 5461.63,2160.97 5483.5,2182.84 5483.5,2253.29 5476.07,2260.72 R540.1@5466.91,2260.72 5465.84,2261.78 5465.84,2283.64 5465.84,2309.15 5475.42,2318.73 U21.16@5475.42,2336.4
LVDS_C_INT: CON6.5 R539.1 R547.2 U21.15 | length 3694
  Top Layer w4: v1(3964.76,641.75) 3979.22,627.29 3979.22,246.89 3982.69,243.42 CON6.5@3982.69,209.68
  L3 w4: v1(3964.76,641.75) 3983.02,660.01 3983.02,680.76 4350.87,1048.61 4350.87,1312.49 4575.82,1537.44 v1(4719.52,1537.44)
  L6 w4: v1(4719.52,1537.44) 4719.52,1457.71 4793.81,1383.42 5243.31,1383.42 5263.9,1362.82 5263.9,1303.97 5298.49,1269.38 v1(5310.79,1269.38)
  Bottom Layer w5: v1(5310.79,1269.38) 5312.24,1269.38 5349.65,1306.8 5349.65,1864.18 5470.69,1985.22 5470.69,2156.5 5510.93,2196.74 5510.93,2254.48 5515.99,2259.54 5527.25,2259.54 R539.1@5527.61,2259.9 5528.61,2260.89 R547.2@5528.61,2283.94 5528.61,2290.31 5495.1,2323.81 U21.15@5495.1,2336.4
"LVDS_D_BL_PWM / PWM_1": CON13.26 CON17.62 J13.1 | length 8730.8
  Top Layer w4: CON17.62@2864.18,2750.44 2866.27,2752.54 2866.27,2825.74 3046.44,3005.92 3310.85,3005.92 3583.15,3278.21 4447.45,3278.21 4556.57,3387.33 v1(4556.57,3492.38) ; J13.1@4487.06,522.73 4487.06,715.29 4554.82,783.05 4710.25,783.05 4741.35,814.15 4741.35,974.41 v1(4724.25,991.51) ; v1(4972.45,5292.75) 4971.03,5294.17 4971.03,5636.76 5149.89,5815.62 5149.89,6034.24 5183.35,6067.7 CON13.26@5183.35,6090.59
  L3 w4: v1(4556.57,3492.38) 4576.89,3512.7 4576.89,3687.21 4615.91,3726.23 4615.91,4201.58 4972.13,4557.8 4972.45,4558.12 v1(4972.45,5292.75)
  Bottom Layer w4: v1(4556.57,3492.38) 4602.69,3492.38 4628.21,3466.85 4739.27,3466.85 5195.74,3010.38 5195.74,1910.31 5232.43,1873.62 5232.43,1752.55 4709.68,1229.8 4709.68,1006.08 v1(4724.25,991.51)
LVDS_D_HPD: CON13.6 R542.1 R550.2 U21.18 | length 4698.7
  Top Layer w4: CON13.6@5577.05,6090.59 5577.05,6067.23 5602.97,6041.31 5602.97,5747.44 5711.89,5638.52 v1(5711.89,5620.03)
  Top Layer w5: v1(5416.58,2306.43) 5416.58,2310.05 R550.2@5431.51,2324.97
  L3 w4: v1(5416.58,2306.43) 5416.58,2276.44 5439.69,2253.34 5645.52,2253.34 5679.1,2286.92 5679.1,2844.71 5871.32,3036.93 5871.32,3212.97 6217.5,3559.15 6217.5,5124.28 5721.76,5620.03 v1(5711.89,5620.03)
  Bottom Layer w4: v1(5416.58,2306.43) 5418.83,2306.43 5436.05,2323.65 U21.18@5436.05,2336.4
  Bottom Layer w5: R542.1@5415.85,2285.83 5415.85,2305.7 v1(5416.58,2306.43)
LVDS_D_INT: CON13.5 R541.1 R549.2 U21.17 | length 4781.7
  Top Layer w4: CON13.5@5596.73,6090.59 5596.73,6062.66 5615.46,6043.94 5615.46,5748.08 v1(5728.51,5635.03)
  Top Layer w5: v1(5440.55,2305.1) 5457,2321.55 R549.2@5457,2324.9
  L3 w4: v1(5440.55,2305.1) 5420.44,2325.21 5410.44,2325.21 5400.43,2315.21 5400.43,2279.98 5435.63,2244.78 5651.46,2244.78 5689.2,2282.52 5689.2,2839.53 5882.13,3032.46 5882.13,3208.64 6225.68,3552.2 6225.68,5129.57 5728.51,5626.74 v1(5728.51,5635.03)
  Bottom Layer w4: v1(5440.55,2305.1) 5455.73,2320.28 U21.17@5455.73,2336.4
  Bottom Layer w5: v1(5440.55,2305.1) 5441.45,2304.2 R541.1@5441.45,2285.62
LVDS_E_HPD: CON14.6 R544.1 R552.2 U21.20 | length 4759.8
  Top Layer w4: CON14.6@6590.46,6090.59 6590.46,5878.63 v1(6593.63,5875.46)
  Top Layer w5: v1(5376,2381.51) 5387.67,2393.18 R552.2@5401.82,2393.18
  L3 w4: v1(5376,2381.51) 5360.77,2366.29 5360.77,2293.29 5427.36,2226.7 5659,2226.7 5707.53,2275.24 5707.53,2828.97 5904.35,3025.79 5904.35,3195.91 6242.29,3533.86 6242.3,5170.75 6421.6,5350.06 6421.6,5471.26 6421.6,5703.44 v1(6593.63,5875.46)
  Bottom Layer w5: R544.1@5352.93,2381.4 5375.88,2381.4 v1(5376,2381.51) 5378.13,2383.64 U21.20@5408.49,2383.64
LVDS_E_INT: CON14.5 R543.1 R551.2 U21.19 | length 4727.4
  Top Layer w4: CON14.5@6610.14,6090.59 6610.14,5904.01 v1(6613.51,5900.65)
  Top Layer w5: v1(5376.11,2355.06) 5389.18,2368.12 R551.2@5401.82,2368.12
  L3 w4: v1(5376.11,2355.06) 5370.15,2349.1 5370.15,2297.37 5432.26,2235.26 5654.76,2235.26 5698.26,2278.75 5698.26,2833.61 5893.8,3029.15 5893.8,3201.22 6234.21,3541.63 6234.21,5174.1 6411.41,5351.31 6411.41,5707.65 6576.52,5872.76 6576.52,5884.66 6592.51,5900.65 v1(6613.51,5900.65)
  Bottom Layer w5: R543.1@5352.93,2356.03 5375.14,2356.03 v1(5376.11,2355.06) 5385.02,2363.96 U21.19@5408.49,2363.96
M2_BT_HOST_WAKEUP: CON5.20 R264.2 | length 60.4
  Top Layer w5: CON5.20@5886.23,3662.52 5935.04,3662.52 R264.2@5943.26,3670.74
M2_PCIE_nCLKREQ: R246.2 R446.1 U23.9 | length 256.6
  Top Layer w5: v1(5481.58,3984.71) 5482,3985.14 R246.2@5503.24,3985.14
  L3 w5: v1(5312.03,3964.66) 5327.65,3949.04 5428.67,3949.04 5464.34,3984.71 v1(5481.58,3984.71)
  Bottom Layer w5: R446.1@5310.57,3981.55 5310.77,3981.35 5310.77,3965.92 v1(5312.03,3964.66) 5312.93,3963.76 U23.9@5312.93,3938.54
M2_PCIE_nRST: R247.1 R445.1 U23.8 | length 799.8
  Top Layer w5: R247.1@5965.1,3949.7 v1(5986.03,3949.7)
  L3 w5: v1(5284.61,3965.88) 5284.61,3957.41 5312.58,3929.44 5439.31,3929.44 5453.82,3943.95 5980.28,3943.95 v1(5986.03,3949.7)
  Bottom Layer w5: R445.1@5284.73,3981.55 5284.73,3966 v1(5284.61,3965.88) 5285.84,3965.88 5297.18,3954.54 U23.8@5297.18,3938.54
M2_PCIE_nWAKE: R243.2 R447.1 U23.10 | length 234.4
  Top Layer w5: v1(5476.36,4008.78) 5478.37,4010.79 R243.2@5503.24,4010.79
  L3 w5: v1(5336.82,3964.34) 5339.44,3961.72 5424.49,3961.72 5471.54,4008.78 v1(5476.36,4008.78)
  Bottom Layer w5: U23.10@5328.68,3938.54 5328.68,3956.2 v1(5336.82,3964.34) 5336.41,3964.75 R447.1@5336.41,3981.55
M2_Power_EN: R244.1 R425.1 U35.14 | length 568.7
  Top Layer w5: v1(5543.92,2918.77) 5629.96,2918.77 5675.81,2872.92 5875.34,2872.92 5893.25,2890.83 v1(5893.25,2936.63)
  Bottom Layer w4: v1(5543.92,2918.77) U35.14@5543.92,2954.86 ; R425.1@5877.03,2936.63 R244.1@5984.74,2936.63
  Bottom Layer w5: R425.1@5874.63,2939.03 R425.1@5877.03,2936.63
M2_SD_CLK: CON5.9 R314.2 | length 1890.4
  Top Layer w6: CON5.9@5588.98,3554.25 5641.14,3554.25 v1(5642.34,3553.05) ; R314.2@6097.84,5032.9 6119.66,5032.9 v1(6120.25,5033.48)
  Bottom Layer w6: v1(5642.34,3553.05) 5615.35,3580.05 5615.35,4623.02 5854.65,4862.32 5854.65,4960.66 5927.72,5033.73 6120,5033.73 v1(6120.25,5033.48)
M2_SD_CMD: CON5.11 R312.2 R532.1 | length 1890.6
  Top Layer w6: CON5.11@5588.98,3573.94 5659.88,3573.94 v1(5659.95,3573.87) ; R312.2@6099.78,4953.85 R312.2@6098.9,4953.85 6099.89,4954.84 R532.1@6122.95,4954.84 6122.95,4977.02 v1(6124.15,4978.22)
  Bottom Layer w6: v1(5659.95,3573.87) 5657.91,3573.87 5643.48,3588.3 5643.48,4601.56 5893.24,4851.32 5893.24,4905.83 5940.14,4952.73 5998.95,4952.73 6001.95,4952.73 ccw(c6001.95,4958.73) 6007.95,4958.73 6007.95,4984.8 cw(c6013.95,4984.8) 6013.95,4990.8 6025.95,4990.8 cw(c6025.95,4984.8) 6031.95,4984.8 6031.95,4958.73 ccw(c6037.95,4958.73) 6037.95,4952.73 6068.46,4952.73 6076.61,4952.73 6076.88,4952.47 6098.41,4952.47 v1(6124.15,4978.22)
M2_SD_DATA0: CON5.13 R306.2 R420.1 | length 1890.6
  Top Layer w6: CON5.13@5588.98,3593.62 5729.18,3593.62 v1(5729.22,3593.66) ; R306.2@6070.24,4691 6070.39,4690.86 R420.1@6094.21,4690.86 6094.21,4669.97 v1(6093.45,4669.21)
  Bottom Layer w6: v1(5729.22,3593.66) 5743.49,3593.66 5814.15,3664.32 5814.15,4064.47 5880.31,4130.63 5880.31,4406.58 5885.53,4411.8 5887.67,4413.94 ccw(c5882.56,4419.01) 5887.66,4424.09 5880.88,4430.88 cw(c5885.95,4435.98) 5880.85,4441.06 5941.6,4501.81 cw(c5946.68,4496.71) 5946.68,4503.91 5997.31,4503.91 ccw(c5997.31,4511.11) 6002.38,4506 6027.06,4530.68 cw(c6032.16,4525.59) 6037.25,4530.68 6044.04,4523.89 cw(c6038.94,4518.8) 6044.04,4513.71 6012.33,4482 cw(c6007.25,4487.11) 6007.25,4479.91 5956.62,4479.91 ccw(c5956.62,4472.71) 5951.54,4477.81 5914.8,4441.07 ccw(c5919.89,4435.98) 5914.8,4430.89 5921.59,4424.1 ccw(c5926.68,4429.19) 5931.77,4424.1 5961.48,4453.81 cw(c5966.56,4448.71) 5966.56,4455.91 6017.19,4455.91 ccw(c6017.19,4463.11) 6022.27,4458 6096.25,4531.99 ccw(c6091.15,4537.07) 6098.35,4537.07 6098.35,4573.27 ccw(c6091.15,4573.27) 6091.15,4580.47 6081.55,4580.47 cw(c6081.55,4587.67) 6074.35,4587.67 6074.35,4614.67 6074.35,4623.68 6074.35,4650.11 v1(6093.45,4669.21)
M2_SD_DATA1: CON5.15 R307.2 R421.1 | length 1890.6
  Top Layer w6: CON5.15@5588.98,3613.31 5702.35,3613.31 v1(5705.47,3616.42) ; R307.2@6088.54,4773.74 6111.39,4773.74 R421.1@6112.54,4772.59 6128.89,4756.24 v1(6128.89,4754.87)
  Bottom Layer w6: v1(5705.47,3616.42) 5730.69,3616.42 5775.21,3660.94 5775.21,4062.72 5848.31,4135.82 5848.31,4332.23 5848.31,4335.23 ccw(c5841.11,4335.23) 5841.11,4342.43 5831.51,4342.43 cw(c5831.51,4349.63) 5824.31,4349.63 5824.31,4502.04 cw(c5831.51,4502.04) 5826.4,4507.12 5900.22,4580.93 cw(c5905.3,4575.83) 5905.3,4583.03 5929.44,4583.03 cw(c5929.44,4575.83) 5936.64,4575.83 5936.64,4566.23 cw(c5929.44,4566.23) 5929.44,4559.03 5915.24,4559.03 ccw(c5915.24,4551.83) 5910.16,4556.93 5860.43,4507.2 ccw(c5865.52,4502.11) 5860.43,4497.02 5867.22,4490.23 ccw(c5872.31,4495.32) 5877.4,4490.23 5920.1,4532.93 cw(c5925.18,4527.83) 5925.18,4535.03 5968.94,4535.03 ccw(c5968.94,4542.23) 5976.14,4542.23 5976.14,4551.83 cw(c5983.34,4551.83) 5983.34,4559.03 5986.34,4559.03 6005.72,4559.03 6052.25,4605.56 6052.25,4728.37 6092.56,4768.68 6115.09,4768.68 v1(6128.89,4754.87)
M2_SD_DATA2: CON5.17 R308.2 R422.1 | length 1890.6
  Top Layer w6: CON5.17@5588.98,3632.99 5683.6,3632.99 v1(5684.92,3634.31) ; v1(5895.14,4790.53) 5895.14,4802.41 5911.24,4818.5 R422.1@5923.65,4818.5 5930.45,4818.5 5931.57,4817.39 R308.2@5947.8,4817.39
  Bottom Layer w6: v1(5684.92,3634.31) 5694.85,3644.24 5694.85,4308.41 5694.85,4311.41 cw(c5702.05,4311.41) 5702.05,4318.61 5711.65,4318.61 ccw(c5711.65,4325.81) 5718.85,4325.81 5718.85,4529.57 ccw(c5711.65,4529.57) 5711.65,4536.77 5702.05,4536.77 ccw(c5702.05,4529.57) 5694.85,4529.57 5694.85,4349.81 cw(c5687.65,4349.81) 5687.65,4342.61 5678.05,4342.61 cw(c5678.05,4349.81) 5670.85,4349.81 5670.85,4583.91 cw(c5678.05,4583.91) 5672.94,4588.99 5689.02,4605.06 cw(c5694.09,4599.96) 5699.19,4605.05 5705.97,4598.26 ccw(c5711.06,4603.35) 5716.16,4598.26 5718.28,4600.38 5895.14,4777.25 v1(5895.14,4790.53)
M2_SD_DATA3: CON5.19 R310.2 R423.1 | length 1890.6
  Top Layer w6: CON5.19@5588.98,3652.68 5726.01,3652.68 v1(5727.6,3654.27) ; v1(5861.58,4708.18) 5881.03,4727.64 R310.2@5915.53,4727.64
  Bottom Layer w6: v1(5727.6,3654.27) 5735.57,3662.24 5735.57,4264.94 5758.9,4288.27 5770.73,4300.1 ccw(c5765.63,4305.18) 5772.83,4305.18 5772.83,4309.49 ccw(c5765.63,4309.49) 5765.63,4316.69 5756.03,4316.69 cw(c5756.03,4323.89) 5748.83,4323.89 5748.83,4592.61 cw(c5756.03,4592.61) 5750.92,4597.68 5762.82,4609.58 cw(c5767.91,4604.49) 5773,4609.58 5779.79,4602.79 cw(c5774.7,4597.7) 5779.79,4592.61 5774.92,4587.74 ccw(c5780.03,4582.67) 5772.83,4582.67 5772.83,4354.96 ccw(c5780.03,4354.96) 5780.03,4347.76 5789.63,4347.76 ccw(c5789.63,4354.96) 5796.83,4354.96 5796.83,4572.73 cw(c5804.03,4572.73) 5798.92,4577.8 5858.73,4637.61 ccw(c5853.63,4642.69) 5858.72,4647.78 5851.93,4654.57 cw(c5857.02,4659.66) 5851.91,4664.73 5854.05,4666.87 5861.58,4674.4 v1(5861.58,4708.18)
M2_SD_HOST_WAKEUP: R263.2 R409.2 U21.2 | length 1412.3
  Top Layer w4: v1(5483.54,3638.87) 5485.12,3640.45 R409.2@5503.24,3640.45 R263.2@5503.24,3666.42
  L3 w4: v1(5457.3,2587.68) 5509.62,2640 5575.05,2640 5610.43,2675.38 5610.43,2885.71 5577.98,2918.16 5577.98,3624.89 5545.89,3656.97 5501.64,3656.97 v1(5483.54,3638.87)
  Bottom Layer w4: U21.2@5455.73,2489.95 5455.73,2586.11 v1(5457.3,2587.68)
M2_SUSCLK: R249.1 R444.1 U23.7 | length 830.4
  Top Layer w5: R249.1@5965.1,3922.19 v1(5986.03,3922.19)
  L3 w5: v1(5260.62,3961.66) 5302.75,3919.53 5445.94,3919.53 5460.35,3933.94 5974.28,3933.94 v1(5986.03,3922.19)
  Bottom Layer w5: R444.1@5258.89,3981.55 5258.89,3963.39 v1(5260.62,3961.66) 5266.55,3961.66 5281.43,3946.78 U23.7@5281.43,3938.54
M2_UART_WAKE: D22.2 R352.2 U21.1 | length 1624.8
  Top Layer w4: v1(5437.03,2523.55) 5437.03,2526.67 5468.07,2557.7 5634.5,2557.7 v1(5663.61,2586.81)
  Bottom Layer w4: U21.1@5436.05,2489.95 5436.05,2522.57 v1(5437.03,2523.55) ; v1(5663.61,2586.81) 5637.97,2612.45 5637.97,2931.21 5651.18,2944.42 5651.18,3016.83 5641.77,3026.24 5641.77,3068.48 5681.17,3107.88 5681.17,3181.44 5883.56,3383.83 5883.56,3488.41 5914.5,3519.35 6086.8,3519.35 D22.2@6087.55,3518.59 6087.55,3526.87 6111.15,3550.46 6139.39,3550.46 R352.2@6158.76,3531.08
M2_USB_D+: FL14.A1 R270.2 | length 48.7
  Top Layer w5: v1(5482.87,3493.52) 5488.28,3498.93 5495.4,3498.93 R270.2@5503.24,3491.09
  Bottom Layer w5: FL14.A1@5463.47,3496.33 5466.19,3499.05 5477.34,3499.05 v1(5482.87,3493.52)
M2_USB_D-: FL14.A2 R269.2 | length 48.9
  Top Layer w5: v1(5482.87,3514.58) 5488.51,3508.93 5495.4,3508.93 R269.2@5503.24,3516.77
  Bottom Layer w5: FL14.A2@5463.47,3512.08 5466.49,3509.05 5477.34,3509.05 v1(5482.87,3514.58)
M2_Vendor_DF38: R254.1 U35.11 | length 1073.6
  Top Layer w4: v1(5617.26,3115.94) 5617.26,3096.61 5633.93,3079.94 5633.93,3009.55 v1(5617.55,2993.17)
  Top Layer w5: R254.1@5963.14,3839.65 v1(5984.06,3839.65)
  Bottom Layer w4: U35.11@5591.4,3002.34 5608.38,3002.34 v1(5617.55,2993.17) ; v1(5617.26,3115.94) 5617.26,3178.11 5854.69,3415.53 5854.69,3514.1 5934.97,3594.39 5934.97,3808.69 5965.94,3839.65 v1(5984.06,3839.65)
M2_WDISABLE1: R242.1 R449.1 U24.10 | length 233.3
  Top Layer w5: R242.1@5963.14,4004.73 5970.06,3997.81 6116.06,3997.81 6137.39,3976.48 v1(6137.39,3975.58)
  Bottom Layer w5: R449.1@6140.4,3991.95 6140.4,3978.58 v1(6137.39,3975.58) 6138.3,3975.58 6143.56,3970.31 U24.10@6143.56,3949.86
M2_WDISABLE1_EXP: R226.2 U24.2 U35.5 | length 1199.3
  Top Layer w4: v1(5543.72,3197.12) 5633.78,3197.12 v1(5654.38,3176.52)
  Bottom Layer w4: v1(5543.72,3197.12) 5543.92,3196.92 U35.5@5543.92,3108.88 ; v1(5654.38,3176.52) 5661.74,3176.52 5873.21,3387.98 5873.21,3493.34 5951.91,3572.04 5951.91,3764.17 5997.21,3809.48 6026.72,3838.99 6128.96,3838.99 6142.23,3852.26 6142.23,3860.32 R226.2@6146.96,3865.05 6143.56,3868.45 U24.2@6143.56,3898.68
M2_WDISABLE2: R245.1 R448.1 U24.9 | length 211.1
  Top Layer w5: R245.1@5963.14,3977.22 5973.71,3987.79 6104.96,3987.79 6113.54,3979.2 v1(6113.54,3975.31)
  Bottom Layer w5: R448.1@6114.83,3991.93 6114.83,3976.6 v1(6113.54,3975.31) 6114.07,3975.31 6127.81,3961.57 U24.9@6127.81,3949.86
M2_WDISABLE2_EXP: R227.2 U24.3 U35.6 | length 1178.1
  Top Layer w4: v1(5561.41,3218.94) 5641.48,3218.94 5660.42,3200 v1(5660.42,3198.64)
  Bottom Layer w4: v1(5561.41,3218.94) 5563.6,3216.75 U35.6@5563.6,3108.88 ; v1(5660.42,3198.64) 5661.58,3198.64 5863.73,3400.79 5863.73,3502.05 5943.56,3581.88 5943.56,3769.86 5992.25,3818.55 6020.85,3847.15 6123.9,3847.15 6128.11,3851.36 6128.11,3860.22 R227.2@6123.28,3865.05 ; R227.2@6122.82,3865.05 6127.81,3870.04 U24.3@6127.81,3898.68
MIC_BIAS: C208.1 R204.2 U19.14 | length 374.2
  Top Layer w12: C208.1@5028.45,1070.22 5029.04,1069.63 5029.64,1069.04 5056.4,1069.04 5064.17,1061.27 U19.14@5093.89,1061.27
  Top Layer w15: R204.2@4960.91,876.37 4941.09,876.37 4917.99,899.48 4917.99,1020.76 4966.86,1069.63 C208.1@5029.04,1069.63
MIC_PRESNT: R201.2 R202.1 U20.16 | length 117.7
  Top Layer w5: U20.16@5276.53,512.44 5276.53,504.65 5289.16,492.02 R201.2@5355.87,492.02 R202.1@5355.87,517.41
MICP: C303.1 FB8.2 U20.6 | length 403.1
  Top Layer w15: C303.1@4989.7,785.64 C303.1@4990.5,786.43 ; FB8.2@4990.5,816.16 C303.1@4990.5,786.43 ; U20.6@5256.85,650.24 5256.85,684.5 5256.69,684.66 5256.69,702.92 5227.63,731.98 5012.98,731.98 4990.5,754.46 C303.1@4990.5,786.43
MIPI_IRQ: CON6.3 U21.7 | length 3771.9
  Top Layer w4: v1(5565.47,2482.39) 5569.76,2478.1 5569.76,2320.21 5610.63,2279.34 v1(5631.85,2279.34)
  Top Layer w6: CON6.3@3943.32,209.68 v1(3943.31,252.57)
  L3 w4: v1(3943.31,252.57) 3931.65,264.23 3931.65,448.5 4400.85,917.7 4400.85,1265.24 4547.69,1412.08 v1(4591.95,1412.08)
  L6 w4: v1(4591.95,1412.08) 4751.26,1412.08 4788.36,1374.99 5236.14,1374.99 5252.34,1358.79 5252.34,1302.58 5301.36,1253.57 5336.18,1253.57 v1(5338.69,1251.05)
  Bottom Layer w4: v1(5338.69,1251.05) 5368.48,1280.84 5368.48,1837.05 5493.17,1961.74 5493.17,2148.83 5623.68,2279.34 v1(5631.85,2279.34) ; U21.7@5562.04,2462.38 5562.04,2478.95 v1(5565.47,2482.39)
NetC4_1: C4.1 R1.2 | length 32.4
  Top Layer w8: R1.2@2346.51,712.1 2348.98,709.64 C4.1@2348.98,680.75
NetC4_2: C4.2 L1.1 U1.26
NetC8_2: C8.2 U1.30 | length 152.6
  Top Layer w8: C8.2@2368.6,345.91 2368.6,349.61 2402.73,383.74 2402.73,436.51 2426.43,460.2 U1.30@2440.76,460.2
NetC9_1: C9.1 R5.2 | length 32.8
  Top Layer w8: C9.1@2682.31,298.48 2686.32,294.47 R5.2@2686.32,267.31
NetC9_2: C9.2 L2.1 U1.10
NetC13_2: C13.2 R6.1 U1.23 | length 158
  Top Layer w8: C13.2@2418.7,706.04 2430.45,694.29 2430.45,644.14 2437.76,636.84 2451.92,636.84 2451.92,635.35 2486.01,601.26 U1.23@2486.01,584.25
NetC14_2: C14.2 R6.2 | length 40.7
  Top Layer w8: R6.2@2451.53,665.87 2451.53,705.12 C14.2@2452.58,706.16
NetC15_2: C15.2 R7.1 U1.7 | length 147.9
  Top Layer w8: U1.7@2584.51,395.25 2584.51,340.02 2586.45,338.09 2594.78,338.09 2608.18,324.69 2608.18,278.32 C15.2@2619.66,266.84
NetC16_2: C16.2 R7.2 | length 42.1
  Top Layer w8: R7.2@2586.45,308.56 2586.45,266.91 C16.2@2586.77,266.59
NetC17_2: C17.2 R11.1 U1.18 | length 155.3
  Top Layer w8: U1.18@2584.51,584.25 2584.51,604.53 2613.94,633.96 R11.1@2613.94,636.25 2628.51,636.25 2637.1,644.84 2637.1,694.78 C17.2@2647.31,704.99
NetC18_2: C18.2 R11.2 | length 39.5
  Top Layer w8: C18.2@2613.24,704.99 2613.94,704.29 R11.2@2613.94,665.78
NetC19_2: C19.2 U1.24 | length 94.6
  Top Layer w10: C19.2@2409.27,635.98 2409.27,608.39 2433.41,584.25 U1.24@2466.31,584.25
